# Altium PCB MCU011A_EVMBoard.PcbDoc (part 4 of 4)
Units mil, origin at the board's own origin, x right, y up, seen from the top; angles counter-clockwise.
Board outline 10115 x 9285 mil, 4 copper layers (Top Layer, GND, PWR, Bottom Layer), stack 61.2 mil thick; 438 components, 207 nets, 1196 pads, 248 vias.
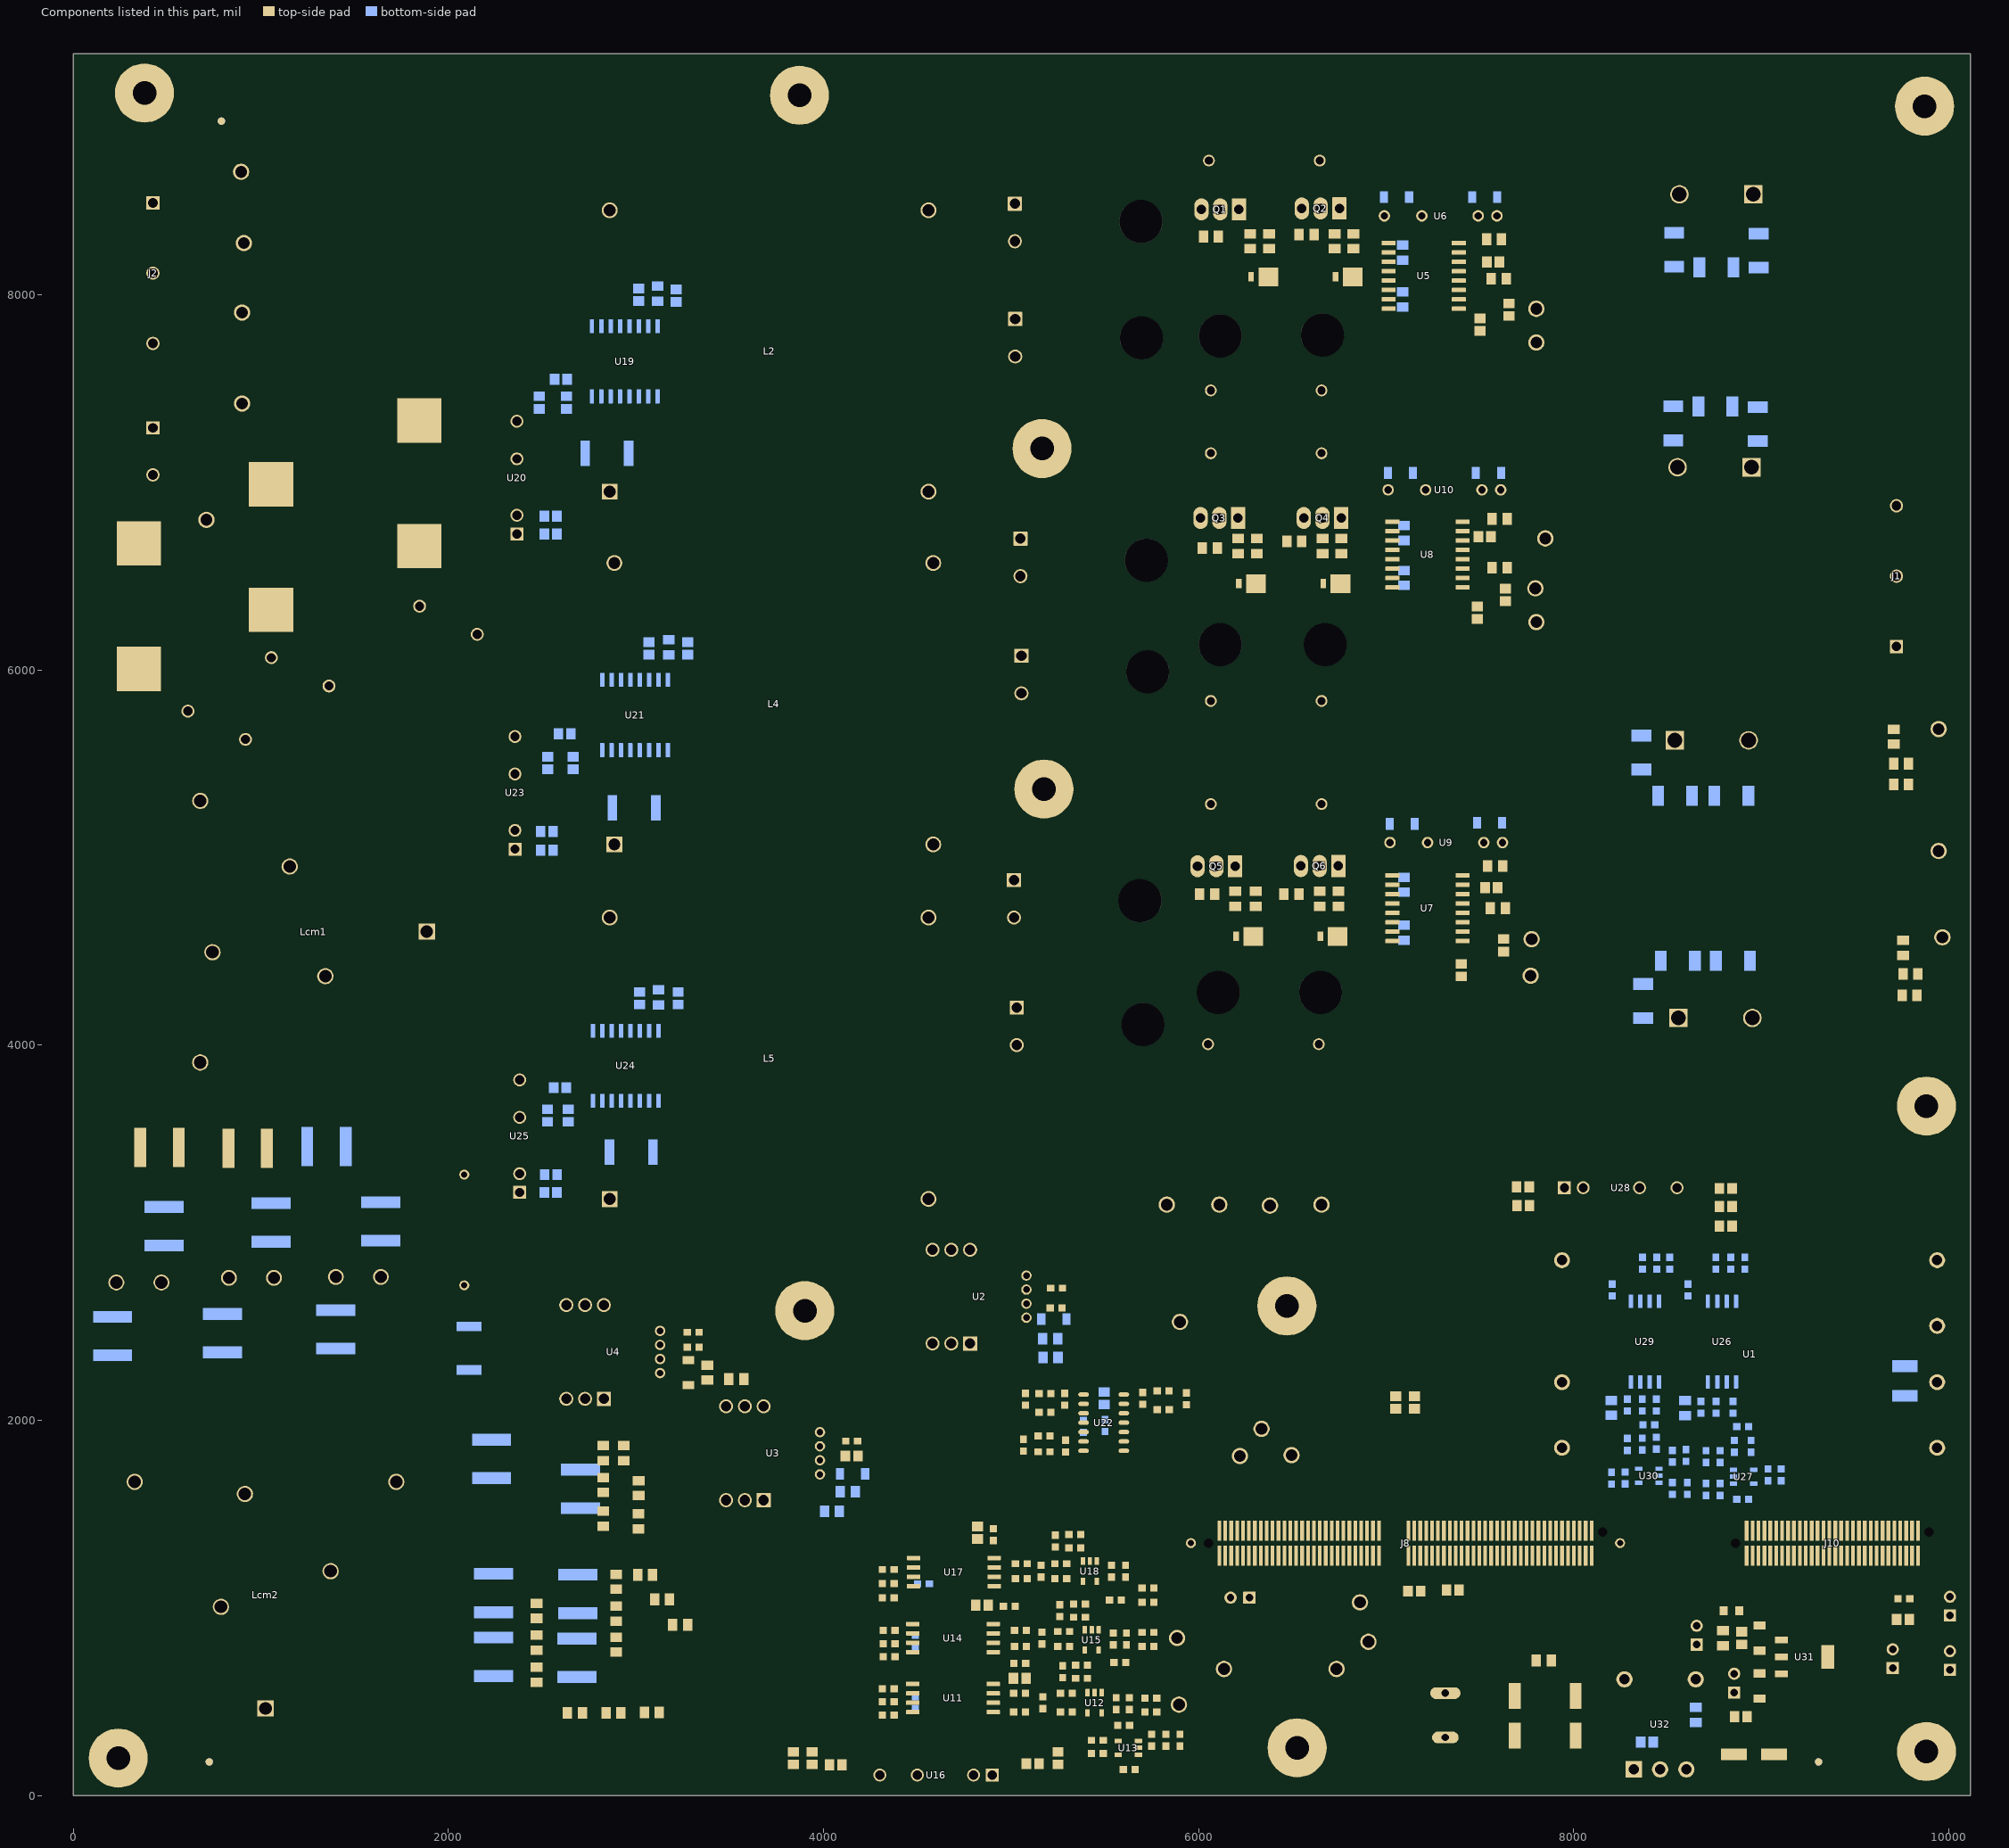
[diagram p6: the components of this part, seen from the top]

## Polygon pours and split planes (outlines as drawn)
V_N_MEAS on Top Layer "TOP_LAYER_V_N_MEAS_P268" (solid, remove dead copper, pour order 268): 35 vertices, not listed, extent 2437,674 2985,1461
NetCx4_1 on Top Layer "PWR" (solid, remove dead copper, pour order 214): 30 vertices, not listed, extent 155,2680 765,4040
NetCx5_1 on Top Layer "PWR" (solid, remove dead copper, pour order 216): 23 vertices, not listed, extent 575,2690 1180,5360
NetRT1_1 on Top Layer "PWR" (solid, remove dead copper, pour order 202): 1665,6745 1665,6450 1665,6420 1780,6305 1840,6305 1890,6305 1915,6330 2005,6420 2005,6530 2005,6735 1965,6775 1960,6780 1700,6780
NetRT3_1 on Top Layer "PWR" (solid, remove dead copper, pour order 200): 905,6425 885,6405 885,6365 885,6095 990,5990 1110,5990 1220,6100 1220,6215 1220,6405 1180,6445 1170,6455 1094.37,6455 935,6455
NetRT2_1 on Top Layer "PWR" (solid, remove dead copper, pour order 198): 240,6125 235,6125 210,6100 200,6090 200,5915 200,5840 215,5825 295,5745 630,5745 675,5790 675,6020 570,6125
V_L2 on Top Layer "V_L2" (solid, remove dead copper, pour order 194): 24 vertices, not listed, extent 65,6505 1050,8395
V_L1 on Top Layer "V_L1" (solid, remove dead copper, pour order 192): 25 vertices, not listed, extent 320,7220 2020,8775
NetD7_1 on Top Layer "TOP_LAYER_NETD7_1_P084" (solid, remove dead copper, pour order 84): 19 vertices, not listed, extent 6320,7985 6540,8270
NetD8_1 on Top Layer "TOP_LAYER_NETD8_1_P086" (solid, remove dead copper, pour order 86): 6795,8270 6870,8270 6880,8260 6885,8255 6885,8035.5 6870,8025 6785,8025 6770,8045 6770,8160 6770,8175 6790,8195 6790,8240 6790,8265
NetD12_1 on Top Layer "TOP_LAYER_NETD12_1_P090" (solid, remove dead copper, pour order 90): 6730,6645 6805,6645 6815,6635 6820,6630 6820,6410 6800,6400.5 6730,6400.5 6705,6410 6705,6420 6705,6535 6705,6550 6725,6570 6725,6615 6725,6640
NetD10_1 on Top Layer "TOP_LAYER_NETD10_1_P092" (solid, remove dead copper, pour order 92): 19 vertices, not listed, extent 6255,6360 6475,6645
NetD11_1 on Top Layer "TOP_LAYER_NETD11_1_P094" (solid, remove dead copper, pour order 94): 6715,4770 6790,4770 6800,4760 6805,4755 6805,4520.5 6785,4515 6710,4515 6690,4530 6690,4535 6690,4660 6690,4675 6710,4695 6710,4740 6710,4765
NetD9_1 on Top Layer "TOP_LAYER_NETD9_1_P096" (solid, remove dead copper, pour order 96): 17 vertices, not listed, extent 6240,4485 6460,4770
VBUSP on Top Layer "TOP_LAYER_VBUSP_P158" (solid, remove dead copper, pour order 158): 78 vertices, not listed, extent 4860,4806 9870,9195
V_M on Top Layer "TOP_LAYER_V_M_P160" (solid, remove dead copper, pour order 160): 67 vertices, not listed, extent 6350,3925 9760,8595
V_M on Top Layer "TOP_LAYER_V_M_P172" (solid, remove dead copper, pour order 172): 18 vertices, not listed, extent 6335,3730 8673.94,4160
NetC109_1 on Top Layer "PWR" (solid, remove dead copper, pour order 232): 26 vertices, not listed, extent 8585,655 9410,820
GND on Top Layer "PWR" (solid, remove dead copper, pour order 236): 17 vertices, not listed, extent 8865,816.46 9150,930
5V on Top Layer "PWR" (solid, remove dead copper, pour order 240): 23 vertices, not listed, extent 8835,550 9195,680
GND on Top Layer "PWR" (solid, remove dead copper, pour order 242): 8945,540 8910,505 8910,430 8910,340 8965,285 9000,250 9000,200 9015,200 9020,195 9130,195 9130,445 9115,460 9035,540 9005,540
12V on Top Layer "PWR" (solid, remove dead copper, pour order 244): 7250,485 7515,485 7535,465 7540,460 7690,460 7720,460 7740,480 7820,560 7820,748.54 7313.54,748.54 7240,675 7220,655 7220,515
NetC105_2 on Top Layer "PWR" (solid, remove dead copper, pour order 248): 24 vertices, not listed, extent 7855,100 8364.39,750
NetC107_1 on Top Layer "PWR" (solid, remove dead copper, pour order 250): 25 vertices, not listed, extent 8580.04,90 8920,585
V_L3 on Top Layer "V_L3" (solid, remove dead copper, pour order 196): 30 vertices, not listed, extent 390,6875 1365,7985
NetCm1_1 on Top Layer "PWR" (solid, remove dead copper, pour order 264): 29 vertices, not listed, extent 1830,807.5 2310,2770
Q1_SOURCE on Bottom Layer "BOTTOM_LAYER_Q1_SOURCE_P266" (solid, remove dead copper, pour order 266): 20 vertices, not listed, extent 5889,8017 6589,8551
NetCm1_1 on Bottom Layer "PWR" (solid, remove dead copper, pour order 228): 2253,1714 2123,1714 2103,1694 2088,1679 2088,1664 2088,1599 2093,1594 2133,1554 2193,1554 2358,1554 2373,1569 2393,1589 2393,1624 2393,1699 2378,1714
NetCm1_1 on Bottom Layer "PWR" (solid, remove dead copper, pour order 226): 2140,1010 2110,1010 2058,981 2058,835 2115,810 2155,810 2360,810 2370,820 2385,835 2385,870 2385,985 2360,1010
V_N_MEAS on Bottom Layer "PWR" (solid, remove dead copper, pour order 224): 2705,1565 2575,1565 2555,1545 2540,1530 2540,1515 2540,1450 2545,1445 2585,1405 2645,1405 2810,1405 2825,1420 2845,1440 2845,1475 2845,1550 2830,1565
V_N_MEAS on Bottom Layer "PWR" (solid, remove dead copper, pour order 222): 2550,1005 2545,1005 2535,995 2530,990 2530,840 2530,771 2540,753 2584,753 2814,753 2825,771 2825,865 2825,980 2800,1005
V_EARTH on Bottom Layer "PWR" (solid, remove dead copper, pour order 220): 21 vertices, not listed, extent 130,3359.3 1280,7081
NetCx1_2 on Bottom Layer "BOTTOM_LAYER_NETCX1_2_P136" (solid, remove dead copper, pour order 136): 22 vertices, not listed, extent 91.65,2274.15 1515,2405
V_M on Bottom Layer "BOTTOM_LAYER_V_M_P162" (solid, remove dead copper, pour order 162): 18 vertices, not listed, extent 6320,5210 6820,6820
V_M on Bottom Layer "BOTTOM_LAYER_V_M_P164" (solid, remove dead copper, pour order 164): 31 vertices, not listed, extent 6310,8280 8720,9200
V_M on Bottom Layer "BOTTOM_LAYER_V_M_P168" (solid, remove dead copper, pour order 168): 19 vertices, not listed, extent 6270,7090 6750,8455.73
VBUSN on Bottom Layer "BOTTOM_LAYER_VBUSN_P170" (solid, remove dead copper, pour order 170): 92 vertices, not listed, extent 4856,3462.5 9771,7720
RSH1_1 on Bottom Layer "BOTTOM_LAYER_RSH1_1_P114" (solid, remove dead copper, pour order 114): 20 vertices, not listed, extent 2930,2850 4595,7231.77
RSH2_1 on Bottom Layer "BOTTOM_LAYER_RSH2_1_P118" (solid, remove dead copper, pour order 118): 20 vertices, not listed, extent 3078.7,1993.98 3586.49,5304.05
RSH3_1 on Bottom Layer "BOTTOM_LAYER_RSH3_1_P120" (solid, remove dead copper, pour order 120): 17 vertices, not listed, extent 2475,2580 3200.89,3506.77
V_M on Bottom Layer "BOTTOM_LAYER_V_M_P178" (solid, remove dead copper, pour order 178): 20 vertices, not listed, extent 6270,3960 6797.5,4976.06
Q5_SOURCE on Bottom Layer "BOTTOM_LAYER_Q5_SOURCE_P180" (solid, remove dead copper, pour order 180): 28 vertices, not listed, extent 5860,4540 6580,5065
NetCx4_2 on Bottom Layer "BOTTOM_LAYER_NETCX4_2_P182" (solid, remove dead copper, pour order 182): 410,3240 380,3210 380,3105 1735,3105 1745,3115 1745,3225 1730,3240
V_C on Bottom Layer "BOTTOM_LAYER_V_C_P152" (solid, remove dead copper, pour order 152): 34 vertices, not listed, extent 190,1505 2965,2161.93
V_B on Bottom Layer "BOTTOM_LAYER_V_B_P150" (solid, remove dead copper, pour order 150): 24 vertices, not listed, extent 1625,1140 3740,1735
V_A on Bottom Layer "BOTTOM_LAYER_V_A_P146" (solid, remove dead copper, pour order 146): 20 vertices, not listed, extent 980,350 4820,2461.93
NetU4_3 on Bottom Layer "Power-No Net" (solid, pour order 122): 18 vertices, not listed, extent 2472.79,2075 2917.8,2660
NetU2_3 on Bottom Layer "Power-No Net" (solid, pour order 44): 18 vertices, not listed, extent 4427.79,2365 4872.8,2965
NetU3_3 on Bottom Layer "Power-No Net" (solid, pour order 54): 19 vertices, not listed, extent 3322.09,1530 3772.09,2130
V_M on GND "GND_V_M_P190" (solid, remove dead copper, pour order 190): 21 vertices, not listed, extent 8165,2570 9198,4150
GND on GND "GND_GND_P108" (solid, remove dead copper, pour order 108): 66 vertices, not listed, extent 2312.5,7.49 10088.55,8700
V_N_MEAS on GND "GND_V_N_MEAS_P176" (solid, remove dead copper, pour order 176): 32 vertices, not listed, extent 2025,10 4545,2288.01
NetLcm1_6 on GND "PWR" (solid, remove dead copper, pour order 208): 19 vertices, not listed, extent 790,4250 1450,5955
NetLcm1_2 on PWR "PWR" (solid, remove dead copper, pour order 210): 19 vertices, not listed, extent 1115,4880 2190,6235
NetLcm1_4 on PWR "PWR" (solid, remove dead copper, pour order 206): 28 vertices, not listed, extent 320,4380 1025,5715
NetCx3_1 on PWR "PWR_NETCX3_1_P188" (solid, remove dead copper, pour order 188): 18 vertices, not listed, extent 1275,1105 1514.17,2835
NetCx2_1 on PWR "PWR_NETCX2_1_P186" (solid, remove dead copper, pour order 186): 870,1665 870,1565 940,1495 945,1495 1040,1495 1125,1609.75 1125,2380 890,2615 890,2805 840,2855 730,2855 690,2815 690,2514 810,2400 870,2340
NetCx1_1 on PWR "PWR_NETCX1_1_P184" (solid, remove dead copper, pour order 184): 30 vertices, not listed, extent 85,835 1050,2825
NetD1_2 on PWR "PWR_NETD1_2_P154" (solid, remove dead copper, pour order 154): 29 vertices, not listed, extent 4445,7835 6195,8555
NetD2_2 on PWR "PWR_NETD2_2_P156" (solid, remove dead copper, pour order 156): 23 vertices, not listed, extent 4400,6035 6145,6810
NetD3_2 on PWR "PWR_NETD3_2_P174" (solid, remove dead copper, pour order 174): 27 vertices, not listed, extent 4475,4150 6140,4945
5V on PWR "PWR" (solid, remove dead copper, pour order 254): 35 vertices, not listed, extent 6515,505 9915,1665
3.3V on PWR "PWR" (solid, remove dead copper, pour order 260): 82 vertices, not listed, extent 4135,160 9755,3115
5V on PWR "PWR" (solid, remove dead copper, pour order 262): 67 vertices, not listed, extent 2545,75.36 5395,3330
NetCx6_1 on PWR "PWR" (solid, remove dead copper, pour order 218): 25 vertices, not listed, extent 1470,2695 1965,4690

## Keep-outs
Keep-Out Layer:
  text ".Layer_Name" at 577,-858.49 h60

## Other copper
Top Layer:
  text ".Layer_Name" at 577,-858.49 h60
GND:
  pour cut-out: 3575,1355 3576,447 3607,447 3607,1347 3599,1355
  pour cut-out: 2029,1751 2373,1751 2386,1738 2386,1253 2416,1241 2416,762 2026,762 2026,1526
  pour cut-out: 2300,7065 2610,7065 2680,7016 2680,6870.1 2767.6,6782.5 3170,6782.5 3170,7325 3170,7610 2755,7610 2300,7610 2300,7545 2300,7407.5
  pour cut-out: 2295,5719.53 2295,5415 2375,5335 2610,5335 2690,5255 2690,4990 2772.5,4907.5 3157.5,4907.5 3260,5010 3260,5660 3185,5735 2295,5735
  pour cut-out: 2245,3902 2245,3675 2310,3525 2380,3525 2605,3525 2700,3430 2700,3053 2746,3007 3212,3007 3265,3097 3265,3300 3265,3715 3165,3815 2680,3815 2525,3970 2310,3970
  pour cut-out: 2485,2710 2485,2540 2605,2465 3000,2465 2995,2755 2520,2755
  pour cut-out: 4250,2999.36 4250,2777.5 4270,2757.5 4800,2757.5 4830,2787.5 4830,3022.5 4740,3082.5 4740,3297.5 4705,3317.5 4470,3317.5 4435,3297.5 4435,3082.5 4255,3012.5
  pour cut-out: 4325,2590 4795,2590 4850,2535 4850,2370 4780,2300 4355,2300 4270,2365 4270,2531.33
  pour cut-out: 3375,2200 3310,2135 3310,2010 3455,1865 3730,1865 3845,1980 3870,1980 3870,2140 3810,2200
  pour cut-out: 6247.5,2825 6692.5,2825 6692.5,2385 6252.5,2385 6247.5,2400
  pour cut-out: 3719.38,2741.25 3719.38,2421.25 3734.38,2401.25 4059.38,2401.25 4084.37,2426.25 4084.37,2751.25 4059.37,2770 3740.62,2770
Bottom Layer:
  region net Q3_SOURCE: 6050,6873.98 6050,6688.52 6063.52,6675 6335,6675 6335,6825 6460,6950 6560,6950 6595,6910 6595,6770 6375,6530 5965,6530 5930,6565 5930,6875 5960,6905 6020,6905
  text ".Layer_Name" at 577,-858.49 h60

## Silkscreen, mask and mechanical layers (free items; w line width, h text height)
Top Overlay:
  region: 3075,8855 2775,8855 2775,8755 3075,8755
  lines w7: 5115,500 5125,490 5125,380 ; 5140,1355 5140,1315 5180,1275 5195,1275 ; 5160,1040 5175,1006 5175,940 5205,910 ; 5215,380 5215,485 5230,500
  lines w10: 608,7240 1060,7240 1368,7548 1460,7548 1626,7714 ; 608,7657 1443,7657 1512,7726
  text "'.PRJ_Number'.PCB_Rev-" at 2000,8995 h108.27
  text "C2000 MCU  / THREE PHASE VIENNA RECTIFIER BOARD / TIEVM-VIENNARECT" at 6133,8962 h100.83
  text "Three Phase Input VL-N  / 110Vrms, 60Hz, 4 Amps or / 220Vrms, 50Hz, 4 Amps" at 1122,8197 h70.83
  text "DC 500V-800V Output  / Pmax 1.2KW at 110 Vrms  / Pmax 2.4 KW at 220Vrms" at 10007,7127 h70.83 r90
  text "Fuse F1, F2 & F3 F4AL250V / Installed on XF1, XF2 & XF3" at 1462,6628 h72.83 r90
  text "Input / 12V DC / 1Amps" at 6808,124 h70.83
  text ".Layer_Name" at 577,-858.49 h60
Bottom Overlay:
  lines w7: 8190,1945 8320,1945 8326.5,1938.5 ; 8215,2275 8230,2275 8265,2240 8265,2175 8280,2160 8320,2160 8325,2155 ; 8475,2000 8485,2010 ; 8795,2145 8805,2155 8810,2155 8945,2155
  text ".Layer_Name" at 577,-858.49 h60
Top Paste:
  text ".Layer_Name" at 577,-858.49 h60
Bottom Paste:
  text ".Layer_Name" at 577,-858.49 h60
Top Solder:
  text ".Layer_Name" at 577,-858.49 h60
  text ".Layer_Name" at 577,-858.49 h60
Bottom Solder:
  text ".Layer_Name" at 577,-858.49 h60
Drill Guide:
  text ".Layer_Name" at 577,-858.49 h60
M1 Board Outline:
  the board outline again, w10
  text ".Layer_Name" at 577,-858.49 h60
M2 Board Dimensions:
  rectangle: 0,-275 125,-150
  rectangle: 125,-400 500,-275
  lines w7: 0,-275 1000,-275 ; 125,-400 125,-150 ; 250,-400 250,-150 ; 500,-400 500,-150 ; 750,-400 750,-150 ; 0,-400 1000,-400 1000,-150 0,-150 0,-400
  text ".Layer_Name" at 577,-858.49 h60
M3 3D STEP Top:
  text ".Layer_Name" at 577,-858.49 h60
M4 3D STEP Bottom:
  text ".Layer_Name" at 577,-858.49 h60
M5 Assembly Top:
  lines w10: -292,-930.17 6308,-930.17 ; -292,-726.83 6310,-726.83 ; -292,-523.5 -292,-1133.5 3713,-1133.5 6310,-1133.5 6310,-523.5 -291.5,-523.5 -291.5,-1133.5 1284,-1133.5 ; 2173,-1133.5 2173,-523.5 ; 3440,-726.83 3440,-523.5 ; 4280,-726.83 4280,-523.5 ; 4902,-1140 4902,-937.17
  text "COMPONENTS MARKED 'DNP' SHOULD NOT BE POPULATED." at 1153.5,-318.5 h60
  text "ASSEMBLY VARIANT:" at 1153,-434 h60
  text ".VariantName" at 2189,-434 h60
  text "PCB VIEWED FROM TOP SIDE" at -228.5,-655.67 h60
  text "BOARD #:" at 2248,-655.67 h60
  text ".PRJ_Number" at 2793.5,-655.67 h60
  text "REV:" at 3638,-655.67 h60
  text ".PCB_Rev" at 3929.5,-655.67 h60
  text "SVN REV:" at 4476,-655.67 h60
  text ".VersionControl_RevNumber" at 4982,-655.67 h60
  text "TID #:" at 2248,-859 h60
  text ".TID" at 2793.5,-859 h60
  text "PLOT NAME =" at -228.5,-1064.34 h60
  text ".plot_File_Name" at 577,-1064.34 h60
  text "GENERATED    :" at 2250,-1064.34 h60
  text ".Print_Date" at 3119.5,-1064.34 h60
  text ".Print_Time" at 3848.5,-1064.34 h60
  text "TEXAS INSTRUMENTS" at 5113,-1064.34 h60
M6 Assembly Bottom:
  lines w10: -292.5,-727.33 6309.5,-727.33 ; -290.5,-930.67 6309.5,-930.67 ; 1115.5,-1140.5 1115.5,-937.67 ; 1737.5,-727.33 1737.5,-524 ; 2577.5,-727.33 2577.5,-524 ; 3844.5,-1134 3844.5,-524 ; 4733.5,-1134 6309,-1134 6309,-524 -292.5,-524 -292.5,-1134 2304.5,-1134 6309.5,-1134 6309.5,-524
  text "COMPONENTS MARKED 'DNP' SHOULD NOT BE POPULATED." at 6102,-318 h60
  text ".VariantName" at 5058,-434 h60
  text "ASSEMBLY VARIANT:" at 6097,-434 h60
  text ".VersionControl_RevNumber" at 1035.5,-656.17 h60
  text "SVN REV:" at 1541.5,-656.17 h60
  text ".PCB_Rev" at 2088,-656.17 h60
  text "REV:" at 2379.5,-656.17 h60
  text ".PRJ_Number" at 3224,-656.17 h60
  text "BOARD #:" at 3769.5,-656.17 h60
  text "PCB VIEWED FROM BOTTOM SIDE" at 6246,-656.17 h60
  text ".TID" at 3224,-859.5 h60
  text "TID #:" at 3769.5,-859.5 h60
  text "TEXAS INSTRUMENTS" at 904.5,-1064.84 h60
  text ".Print_Time" at 2169,-1064.84 h60
  text ".Print_Date" at 2898,-1064.84 h60
  text "GENERATED    :" at 3767.5,-1064.84 h60
  text ".plot_File_Name" at 5440.5,-1064.84 h60
  text "PLOT NAME =" at 6246,-1064.84 h60
M9 Title Sheet:
  drawing of 57 lines, arcs and shapes, not listed
  text "1" at 719.34,11039.5 h70
  text "2" at 3215,11039.5 h70
  text "3" at 5704.34,11039.5 h70
  text "4" at 8211.01,11039.5 h70
  text "5" at 10710,11039.5 h70
  text "6" at 13215,11039.5 h70
  text "A" at 15733.5,6998 h70
  text "A" at -416.5,6893.5 h70
  text "B" at 15733.5,4618 h70
  text "B" at -416.5,4513.5 h70
  text "C" at 15733.5,2243 h70
  text "C" at -416.5,2138.5 h70
  text "PROJECT TITLE:" at 12693.5,277.5 h45
  text ".PRJ_Title" at 12743.5,144.17 h70
  text "DESIGNED FOR:" at 12693.5,-23.5 h45
  text ".PRJ_Customer" at 12743.5,-163.5 h70
  text "D" at 15733.5,-177 h70
  text "D" at -416.5,-231.5 h70
  text "FILE NAME:" at 12693.5,-323.5 h45
  text ".PCB_File_Name_No_Path" at 12743.5,-443.5 h70
  text "Texas Instruments (TI) and/or its licensors do not warrant the accuracy or completeness of this specification" at 6374,-605.34 h45
  text "ENGINEER:" at 12693.5,-613.5 h45
  text "LAYOUT BY:" at 14198.5,-613.5 h45
  text "or any information contained therein. TI and/or its licensors do not warrant that this design will meet" at 6329.01,-718 h45
  text ".PRJ_Engineer" at 12743.5,-768.49 h70
  text ".PCB_Layout" at 14249,-768.49 h70
  text "the specifications, will be suitable for your application or fit for any particular purpose, or will operate in" at 6329.01,-830.67 h45
  text ".Layer_Name" at 577,-858.49 h60
  text "ALTIUM DESIGNER VERSION:" at 14198.5,-923.5 h45
  text "an implementation. TI and/or its licensors do not warrant that the design is production worthy. You should" at 6329.01,-943.33 h45
  text "completely validate and test your design implementation to confirm the system functionality for your application." at 6374,-1056 h45
  text ".print_Scale" at 12743.5,-1056.83 h70
  text ".Application_BuildNumber" at 14249,-1056.83 h70
  text "1" at 739.84,-1263.5 h70
  text "2" at 3235.5,-1263.5 h70
  text "3" at 5724.84,-1263.5 h70
  text "4" at 8231.51,-1263.5 h70
  text "5" at 10730.5,-1263.5 h70
  text "6" at 14585.5,-1263.5 h70
M10 Fab Notes:
  drawing of 173 lines, arcs and shapes, not listed
  text "DESIGN INFORMATION" at 13728.02,6201 h60
  text "MIN. TRACK WIDTH:" at 13083.46,6021 h60
  text "8" at 14179.7,6021 h60
  text "MIL" at 14334.46,6021 h60
  text "MIN. CLEARANCE:" at 13083.46,5889 h60
  text "0.2" at 14119.7,5889 h60
  text "mm" at 14334.46,5889 h60
  text "MIN. VIA PAD SIZE:" at 13083.46,5757 h60
  text "24" at 14149.71,5757 h60
  text "MIL" at 14334.46,5757 h60
  text "0.05mm (2MIL)" at 13778.46,5615.29 h60
  text "MINIMUM ANNULAR RING" at 12754.23,5611 h60
  text "EXTERNAL" at 14486.46,5611 h60
  text "PER" at 12954.23,5493 h60
  text "IPC-D-275 CLASS 2 LEVEL C" at 13174.23,5493 h60
  text "MIL, HOLES" at 14662.46,5380.71 h60
  text "+/-" at 14270,5380 h60
  text "+/-" at 15124,5380 h60
  text "REGISTRATION TOLERANCES:" at 12754.23,5375 h60
  text "METAL" at 13954,5375 h60
  text "5" at 14530.2,5375 h60
  text "3" at 15363.2,5375 h60
  text "MIL" at 15479.46,5375 h60
  text "+/-" at 15124,5262 h60
  text "HOLE SIZE TOLERANCE (UNLESS OTHERWISE SPECIFIED):" at 12754.23,5257 h60
  text "3" at 15363.2,5257 h60
  text "MIL" at 15479.46,5257 h60
  text "MATERIAL:" at 12679.46,5047.54 h60
  text "FR-4 High Tg" at 13665.9,4907.21 h60
  text "FR-408" at 13100.46,4898.64 h60
  text "OTHER" at 14588.46,4898.64 h60
  text "X" at 13511,4895 h60
  text "62 MIL (1.6mm) +/-10%" at 13420.56,4735.92 h60
  text "THICKNESS:" at 12754.23,4731.64 h60
  text "X" at 13292.4,4731.64 h60
  text "OTHER" at 14705.46,4731.64 h60
  text "TOLERANCE:" at 12754.23,4573.64 h60
  text "X" at 13593.53,4573.64 h60
  text "ANSI IPC-6012 TYPE 3 CLASS 2" at 13780.48,4573.64 h60
  text "OTHER +/-" at 13780.46,4417.64 h60
  text "BOW & TWIST:" at 12754.23,4260.64 h60
  text "X" at 13593.53,4260.64 h60
  text "ANSI IPC-6012 TYPE 3 CLASS 2" at 13780.48,4260.64 h60
  text "OTHER +/-" at 13780.46,4102.13 h60
  text "DRILLING:" at 12679.46,3963.64 h60
  text "REFERENCE:" at 12754.23,3846.64 h60
  text "X" at 13402.46,3846.64 h60
  text "AS SHOWN" at 13589.46,3846.64 h60
  text "X" at 14303.46,3846.64 h60
  text "NC_DRILL FILES" at 14440.46,3846.64 h60
  text "PTH COPPER THICKNESS:" at 12754.23,3688.64 h60
  text "X" at 13884.46,3688.64 h60
  text "20-30 um" at 14021.46,3688.64 h60
  text "OTHER" at 14738.46,3688.64 h60
  text "BOARD FINISH:" at 12679.46,3529.64 h60
  text "SILKSCREEN:" at 12834.68,3411.64 h60
  text "X" at 13783.46,3411.64 h60
  text "TOP" at 13909.46,3411.64 h60
  text "X" at 14293.46,3411.64 h60
  text "BOTTOM" at 14420.46,3411.64 h60
  text "SILKSCREEN COLOR:" at 12834.68,3244.64 h60
  text "X" at 13782.42,3244.64 h60
  text "WHITE" at 13909.46,3244.64 h60
  text "OTHER" at 14420.46,3244.64 h60
  text "X" at 13913.42,3085.44 h60
  text "GREEN" at 14040.46,3085.44 h60
  text "OTHER" at 14658.46,3085.44 h60
  text "SOLDER RESIST COLOR:" at 12834.68,3074.64 h60
  text "X" at 13913.42,2915.44 h60
  text "MATTE" at 14040.46,2915.44 h60
  text "SEMI-GLOSS" at 14658,2914.8 h60
  text "IMMERSION GOLD (ENIG)" at 13740.46,2726.92 h60
  text "ENEPIG" at 15078,2723.64 h60
  text "SURFACE FINISH:" at 12679.46,2722.64 h60
  text "X" at 13553.51,2722.64 h60
  text "IMM. TIN/SILVER OR EQUIV" at 13009,2565.64 h60
  text "OTHER" at 14440.46,2565.64 h60
  text "ARRAY/PANEL:" at 12679.46,2386.64 h60
  text "CUT AND TRIM PER M1 BOARD OUTLINE" at 13740.46,2382.35 h60
  text "N.C. ROUTE" at 13740.46,2230.64 h60
  text "X" at 14419.46,2230.64 h60
  text "V. SCORE" at 14606.46,2230.64 h60
  text "CERTIFICATION:" at 12679.46,2093.64 h60
  text "MATERIALS AND WORKMANSHIP FOR ALL PCBS" at 13404.46,2093.64 h60
  text "TO MEET OR EXCEED THE REQUIREMENTS OF:" at 13404.46,1995.64 h60
  text "X" at 13030.96,1859.13 h60
  text "ANSI IPC-A-600F CLASS ->" at 13169.96,1859.13 h60
  text "X" at 14809.02,1859.13 h60
  text "2" at 14927.96,1859.14 h60
  text "1" at 14612.96,1857.64 h60
  text "3" at 15281.96,1857.64 h60
  text "X" at 13845.02,1699.64 h60
  text "RoHS" at 13981.96,1699.64 h60
  text "OTHER" at 14626.36,1699.64 h60
  text "PER ORDER" at 15023.42,1699.64 h60
  text "ALL BOARDS MUST MEET OR EXCEED UL94-V0 REQUIREMENTS." at 12707,1534 h60
  text "PCB MUST BEAR THE UL94V-0 UL REGISTERED MATERIAL ID NUMBER" at 12707,1414 h60
  text "ADDITIONAL REQUIREMENTS:" at 12679.46,1240.64 h60
  text "MICROSECTION:" at 12754.23,1125.64 h60
  text "YES" at 13659.96,1125.64 h60
  text "REQUIRED" at 14521.46,969.49 h60
  text "BARE BOARD ELEC. TEST:" at 12754.23,966.64 h60
  text "NONE" at 14059.96,966.64 h60
  text "X" at 14394.46,966.64 h60
  text "PER ORDER" at 15113.46,966.64 h60
  text ".Layer_Name" at 577,-858.49 h60
M11 Gerber Information:
  lines w10: -292,-930.17 6308,-930.17 ; -292,-726.83 6310,-726.83 ; -292,-523.5 -292,-1133.5 3713,-1133.5 6310,-1133.5 6310,-523.5 -291.5,-523.5 -291.5,-1133.5 1284,-1133.5 ; 2173,-1133.5 2173,-523.5 ; 3440,-726.83 3440,-523.5 ; 4280,-726.83 4280,-523.5 ; 4902,-1140 4902,-937.17
  text "ALL ARTWORK VIEWED FROM TOP SIDE" at -228.5,-655.67 h60
  text "BOARD #:" at 2248,-655.67 h60
  text ".PRJ_Number" at 2793.5,-655.67 h60
  text "REV:" at 3638,-655.67 h60
  text ".PCB_Rev" at 3929.5,-655.67 h60
  text "SVN REV:" at 4476,-655.67 h60
  text ".VersionControl_RevNumber" at 4982,-655.67 h60
  text "LAYER NAME =" at -228.5,-858.49 h60
  text "TID #:" at 2248,-859 h60
  text ".TID" at 2793.5,-859 h60
  text "PLOT NAME =" at -228.5,-1064.34 h60
  text ".plot_File_Name" at 577,-1064.34 h60
  text "GENERATED    :" at 2250,-1064.34 h60
  text ".Print_Date" at 3119.5,-1064.34 h60
  text ".Print_Time" at 3848.5,-1064.34 h60
  text "TEXAS INSTRUMENTS" at 5113,-1064.34 h60
M12 Stackup:
  drawing of 295 lines, arcs and shapes, not listed
  text "Layer" at 11091.58,10888 h60
  text "Name" at 11501.49,10888 h60
  text "Material" at 12431.23,10888 h60
  text "Thickness" at 13291,10888 h60
  text "Constant" at 13940.84,10888 h60
  text "Board Layer Stack" at 14510.7,10888 h60
  text "1" at 11091.58,10768 h60
  text "Top Overlay" at 11501.49,10768 h60
  text "2" at 11091.58,10648 h60
  text "Top Solder" at 11501.49,10648 h60
  text "Solder Resist" at 12431.23,10648 h60
  text "0.40mil" at 13291,10648 h60
  text "3.5" at 13940.84,10648 h60
  text "3" at 11091.58,10528 h60
  text "Top Layer" at 11501.49,10528 h60
  text "Copper" at 12431.23,10528 h60
  text "2.80mil" at 13291,10528 h60
  text "4" at 11091.58,10408 h60
  text "Dielectric1" at 11501.49,10408 h60
  text "FR-4" at 12431.23,10408 h60
  text "15.00mil" at 13291,10408 h60
  text "4.8" at 13940.84,10408 h60
  text "5" at 11091.58,10288 h60
  text "GND" at 11501.49,10288 h60
  text "Copper" at 12431.23,10288 h60
  text "2.80mil" at 13291,10288 h60
  text "6" at 11091.58,10168 h60
  text "Dielectric 3" at 11501.49,10168 h60
  text "FR-4" at 12431.23,10168 h60
  text "20.00mil" at 13291,10168 h60
  text "4.2" at 13940.84,10168 h60
  text "7" at 11091.58,10048 h60
  text "PWR" at 11501.49,10048 h60
  text "Copper" at 12431.23,10048 h60
  text "2.80mil" at 13291,10048 h60
  text "8" at 11091.58,9928 h60
  text "Dielectric 2" at 11501.49,9928 h60
  text "FR-4" at 12431.23,9928 h60
  text "15.00mil" at 13291,9928 h60
  text "4.2" at 13940.84,9928 h60
  text "9" at 11091.58,9808 h60
  text "Bottom Layer" at 11501.49,9808 h60
  text "Copper" at 12431.23,9808 h60
  text "2.80mil" at 13291,9808 h60
  text "10" at 11091.58,9688 h60
  text "Bottom Solder" at 11501.49,9688 h60
  text "Solder Resist" at 12431.23,9688 h60
  text "0.40mil" at 13291,9688 h60
  text "3.5" at 13940.84,9688 h60
  text "11" at 11091.58,9568 h60
  text "Bottom Overlay" at 11501.49,9568 h60
  text ".Layer_Name" at 577,-858.49 h60
M13 Component Bodies Top:
  text ".Layer_Name" at 577,-858.49 h60
M14 Component Bodies Bottom:
  text ".Layer_Name" at 577,-858.49 h60
M15 Courtyards Top:
  text ".Layer_Name" at 577,-858.49 h60
M16 Courtyards Bottom:
  text ".Layer_Name" at 577,-858.49 h60
Drill Drawing:
  drawing of 181 lines, arcs and shapes, not listed
  text "Symbol" at 12139.43,9450.64 h72
  text "Quantity" at 12440,9450.64 h72
  text "Finished Hole Size" at 12772,9450.64 h72
  text "Plated" at 13408.56,9450.64 h72
  text "Hole Type" at 13667.7,9450.64 h72
  text "Drill Layer Pair" at 14042.86,9450.64 h72
  text "Hole Tolerance" at 14767.19,9450.64 h72
  text "4" at 12440,9326.32 h60
  text "50.00mil (1.270mm)" at 12772,9326.32 h60
  text "NPTH" at 13408.56,9326.32 h60
  text "Round" at 13667.7,9326.32 h60
  text "Top Layer - Bottom Layer" at 14042.86,9326.32 h60
  text "243" at 12440,9202 h60
  text "16.00mil (0.406mm)" at 12772,9202 h60
  text "PTH" at 13408.56,9202 h60
  text "Round" at 13667.7,9202 h60
  text "Top Layer - Bottom Layer" at 14042.86,9202 h60
  text "H" at 12114.15,9192.01 h55.25
  text "5" at 12440,9077.68 h60
  text "28.00mil (0.711mm)" at 12772,9077.68 h60
  text "PTH" at 13408.56,9077.68 h60
  text "Round" at 13667.7,9077.68 h60
  text "Top Layer - Bottom Layer" at 14042.86,9077.68 h60
  text "F" at 12114.15,9067.69 h55.25
  text "2" at 12440,8953.36 h60
  text "33.07mil (0.840mm)" at 12772,8953.36 h60
  text "PTH" at 13408.56,8953.36 h60
  text "Round" at 13667.7,8953.36 h60
  text "Top Layer - Bottom Layer" at 14042.86,8953.36 h60
  text "2" at 12440,8829.04 h60
  text "33.47mil (0.850mm)" at 12772,8829.04 h60
  text "PTH" at 13408.56,8829.04 h60
  text "Round" at 13667.7,8829.04 h60
  text "Top Layer - Bottom Layer" at 14042.86,8829.04 h60
  text "12" at 12440,8704.72 h60
  text "35.43mil (0.900mm)" at 12772,8704.72 h60
  text "PTH" at 13408.56,8704.72 h60
  text "Round" at 13667.7,8704.72 h60
  text "Top Layer - Bottom Layer" at 14042.86,8704.72 h60
  text "D" at 12114.15,8694.73 h55.25
  text "12" at 12440,8580.4 h60
  text "39.37mil (1.000mm)" at 12772,8580.4 h60
  text "PTH" at 13408.56,8580.4 h60
  text "Round" at 13667.7,8580.4 h60
  text "Top Layer - Bottom Layer" at 14042.86,8580.4 h60
  text "12" at 12440,8456.08 h60
  text "40.00mil (1.016mm)" at 12772,8456.08 h60
  text "PTH" at 13408.56,8456.08 h60
  text "Round" at 13667.7,8456.08 h60
  text "Top Layer - Bottom Layer" at 14042.86,8456.08 h60
  text "12" at 12440,8331.76 h60
  text "43.31mil (1.100mm)" at 12772,8331.76 h60
  text "PTH" at 13408.56,8331.76 h60
  text "Round" at 13667.7,8331.76 h60
  text "Top Layer - Bottom Layer" at 14042.86,8331.76 h60
  text "26" at 12440,8207.44 h60
  text "49.21mil (1.250mm)" at 12772,8207.44 h60
  text "PTH" at 13408.56,8207.44 h60
  text "Round" at 13667.7,8207.44 h60
  text "Top Layer - Bottom Layer" at 14042.86,8207.44 h60
  text "18" at 12440,8083.12 h60
  text "50.00mil (1.270mm)" at 12772,8083.12 h60
  text "PTH" at 13408.56,8083.12 h60
  text "Round" at 13667.7,8083.12 h60
  text "Top Layer - Bottom Layer" at 14042.86,8083.12 h60
  text "8" at 12440,7958.8 h60
  text "51.18mil (1.300mm)" at 12772,7958.8 h60
  text "PTH" at 13408.56,7958.8 h60
  text "Round" at 13667.7,7958.8 h60
  text "Top Layer - Bottom Layer" at 14042.86,7958.8 h60
  text "A" at 12114.15,7948.81 h55.25
  text "7" at 12440,7834.48 h60
  text "55.00mil (1.397mm)" at 12772,7834.48 h60
  text "PTH" at 13408.56,7834.48 h60
  text "Round" at 13667.7,7834.48 h60
  text "Top Layer - Bottom Layer" at 14042.86,7834.48 h60
  text "E" at 12114.15,7824.49 h55.25
  text "35" at 12440,7710.16 h60
  text "55.12mil (1.400mm)" at 12772,7710.16 h60
  text "PTH" at 13408.56,7710.16 h60
  text "Round" at 13667.7,7710.16 h60
  text "Top Layer - Bottom Layer" at 14042.86,7710.16 h60
  text "29" at 12440,7585.84 h60
  text "63.00mil (1.600mm)" at 12772,7585.84 h60
  text "PTH" at 13408.56,7585.84 h60
  text "Round" at 13667.7,7585.84 h60
  text "Top Layer - Bottom Layer" at 14042.86,7585.84 h60
  text "M" at 12114.15,7575.85 h55.25
  text "12" at 12440,7461.52 h60
  text "63.39mil (1.610mm)" at 12772,7461.52 h60
  text "PTH" at 13408.56,7461.52 h60
  text "Round" at 13667.7,7461.52 h60
  text "Top Layer - Bottom Layer" at 14042.86,7461.52 h60
  text "6" at 12440,7337.2 h60
  text "64.96mil (1.650mm)" at 12772,7337.2 h60
  text "PTH" at 13408.56,7337.2 h60
  text "Round" at 13667.7,7337.2 h60
  text "Top Layer - Bottom Layer" at 14042.86,7337.2 h60
  text "12" at 12440,7212.88 h60
  text "66.93mil (1.700mm)" at 12772,7212.88 h60
  text "PTH" at 13408.56,7212.88 h60
  text "Round" at 13667.7,7212.88 h60
  text "Top Layer - Bottom Layer" at 14042.86,7212.88 h60
  text "8" at 12440,7088.56 h60
  text "78.74mil (2.000mm)" at 12772,7088.56 h60
  text "PTH" at 13408.56,7088.56 h60
  text "Round" at 13667.7,7088.56 h60
  text "Top Layer - Bottom Layer" at 14042.86,7088.56 h60
  text "11" at 12440,6964.24 h60
  text "125.98mil (3.200mm)" at 12772,6964.24 h60
  text "PTH" at 13408.56,6964.24 h60
  text "Round" at 13667.7,6964.24 h60
  text "Top Layer - Bottom Layer" at 14042.86,6964.24 h60
  text "12" at 12440,6839.92 h60
  text "230.00mil (5.842mm)" at 12772,6839.92 h60
  text "PTH" at 13408.56,6839.92 h60
  text "Round" at 13667.7,6839.92 h60
  text "Top Layer - Bottom Layer" at 14042.86,6839.92 h60
  text "G" at 12114.15,6829.93 h55.25
  text "1" at 12440,6715.6 h60
  text "39.37mil (1.000mm)" at 12772,6715.6 h60
  text "PTH" at 13408.56,6715.6 h60
  text "Slot" at 13667.7,6715.6 h60
  text "Top Layer - Bottom Layer" at 14042.86,6715.6 h60
  text "L" at 12114.15,6705.61 h55.25
  text "1" at 12440,6591.28 h60
  text "39.37mil (1.000mm)" at 12772,6591.28 h60
  text "PTH" at 13408.56,6591.28 h60
  text "Slot" at 13667.7,6591.28 h60
  text "Top Layer - Bottom Layer" at 14042.86,6591.28 h60
  text "K" at 12114.15,6581.29 h55.25
  text "490 Total" at 12440,6466.96 h60
  text "Slot definitions :" at 12139.43,6379.94 h60
  text "Routed Path Length" at 12590.15,6379.94 h60
  text "= Calculated from tool start centre position to tool end centre position." at 13129.89,6379.94 h60
  text "Hole Length" at 12590.15,6330.21 h60
  text "= Routed Path Length + Tool Size = Slot length as defined in the PCB layout" at 12930.09,6330.21 h60
  text ".Layer_Name" at 577,-858.49 h60
M17 Embedded Cavity:
  text ".Layer_Name" at 577,-858.49 h60
M18 Embedded Assembly:
  text ".Layer_Name" at 577,-858.49 h60
M19 Embedded Keepout:
  text ".Layer_Name" at 577,-858.49 h60

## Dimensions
0,-400 to 1000,-400 on M2 Board Dimensions
0,0 to 0,9285 on M2 Board Dimensions
0,0 to 10115,0 on M2 Board Dimensions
